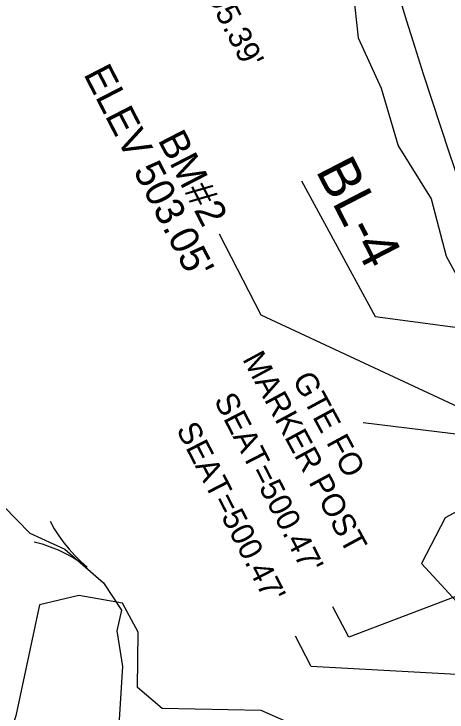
# Model space of a CAD drawing. Extents: x 1534145 to 1537876, y 509021 to 513201.
# Drawn here: x 1535965.3 to 1536040.8, y 511733.6 to 511855.4 of the extents above; entities that cross this region are included whole.
import ezdxf

# ---------------------------------------------------------------- set-up
doc = ezdxf.new("R2010")
doc.units = 0
for name, color, linetype in [('CTL Bench Mark Leader', 7, 'Continuous'), ('CTL Bench Mark Text', 7, 'Continuous'), ('Exist Horizontal Alignment', 7, 'Continuous'), ('Exist Horizontal Baseline Alignment Station Label', 7, 'Continuous'), ('Exist Hydro Stream Flow Arrow CELL', 7, 'Continuous'), ('Exist Hydro Stream or Body of Water', 7, 'Continuous'), ('Exist Right of Way Line', 7, 'Continuous'), ('Exist Structure Major Bridge Seat Top Elevation', 7, 'Continuous'), ('Exist Structure Minor Pipes RCP 15 Inch Invert', 7, 'Continuous'), ('Exist Utilities Other Located Object Leader', 7, 'Continuous'), ('Exist Utilities Other Located Object Text', 7, 'Continuous'), ('Exist Vegetation Woods Line', 7, 'Continuous')]:
    doc.layers.add(name, color=color, linetype=linetype)

msp = doc.modelspace()

# ---------------------------------------------------------------- linework, layer by layer
at = {"layer": 'CTL Bench Mark Leader'}
msp.add_lwpolyline([(1536079.8, 511769.6), (1536008.42, 511802.86), (1536001.11, 511817.02)], dxfattribs=at)
at = {"layer": 'Exist Horizontal Alignment'}
msp.add_arc((1536874.85, 512113.15), 850, 183.46397, 223.9944, dxfattribs=at)
at = {"layer": 'Exist Horizontal Baseline Alignment Station Label'}
msp.add_lwpolyline([(1536015.47, 511826.3), (1536028.3, 511802.67), (1536066.28, 511797.6)], dxfattribs=at)
at = {"layer": 'Exist Hydro Stream Flow Arrow CELL'}
msp.add_line((1535974.11, 511762.02), (1535974.11, 511762.02), dxfattribs=at)
for points in [[(1535971.6, 511766.92), (1535972.28, 511765.62), (1535973.11, 511764.37), (1535973.95, 511763.15), (1535974.86, 511762.03), (1535975.86, 511760.94), (1535976.93, 511759.89), (1535978.03, 511758.92)], [(1535968.77, 511763.32), (1535970.19, 511762.97), (1535971.59, 511762.45), (1535972.97, 511761.91), (1535974.27, 511761.29), (1535975.57, 511760.57), (1535976.84, 511759.77), (1535978.03, 511758.92)]]:
    msp.add_lwpolyline(points, dxfattribs=at)
at = {"layer": 'Exist Hydro Stream or Body of Water'}
msp.add_lwpolyline([(1535946.75, 511770.51), (1535959.25, 511770.95), (1535963.42, 511769.55), (1535968.05, 511764.86), (1535974.11, 511762.02), (1535980.91, 511756.14), (1535984.02, 511751.42), (1535983.21, 511747.78), (1535984.2, 511741.56), (1535983.63, 511732.34), (1535984.87, 511726.77), (1535984.64, 511723.27), (1535982.14, 511717.09)], dxfattribs=at)
at = {"layer": 'Exist Right of Way Line'}
msp.add_arc((1536874.85, 512113.15), 880, 183.46397, 223.9944, dxfattribs=at)
at = {"layer": 'Exist Structure Major Bridge Seat Top Elevation'}
for points in [[(1536083.97, 511769.63), (1536023.69, 511746.66), (1536020.94, 511751.99)], [(1536099.56, 511737.01), (1536017.12, 511741.55), (1536014.37, 511746.89)]]:
    msp.add_lwpolyline(points, dxfattribs=at)
at = {"layer": 'Exist Utilities Other Located Object Leader'}
msp.add_lwpolyline([(1536070, 511778.73), (1536026.2, 511784.1)], dxfattribs=at)
at = {"layer": 'Exist Vegetation Woods Line'}
for points in [[(1535954.04, 511853.16), (1535966.02, 511858.51), (1535970.6, 511870.91), (1535970.15, 511875.74), (1535974.71, 511881.1), (1535988.59, 511888.03), (1536000.97, 511889.59), (1536009.77, 511882.21), (1536016.62, 511871.88), (1536024.49, 511859.38), (1536025.31, 511851.26), (1536029.33, 511842.5), (1536032.33, 511832.43), (1536038.1, 511823.16), (1536040.7, 511813.2), (1536045, 511805.29), (1536048.58, 511798.25), (1536049.61, 511787.84), (1536052.62, 511782.04), (1536051.19, 511773.44), (1536046.44, 511770.73), (1536040.52, 511767.51), (1536036.36, 511759.53)], [(1536036.36, 511759.53), (1536044.62, 511750.63), (1536055.14, 511742.04), (1536060.04, 511732.9), (1536050.95, 511727.97), (1536041.11, 511727.43), (1536031.81, 511731.1), (1536016.97, 511730.12), (1536008.4, 511733.89), (1535991.12, 511734.21)], [(1535991.12, 511734.21), (1535986.81, 511737.92), (1535986.94, 511747.54), (1535984.2, 511752.64), (1535976.56, 511753.95), (1535969.71, 511752.34), (1535965.6, 511732.98), (1535962.22, 511722.69), (1535952.18, 511720.66), (1535941.4, 511721.15), (1535936.11, 511722.2), (1535929.54, 511726.22), (1535927.65, 511729.7), (1535915.01, 511733.19), (1535905.33, 511731.62), (1535892.86, 511729.74), (1535881.99, 511734.13), (1535876.96, 511731.39), (1535869.12, 511724.27)]]:
    msp.add_lwpolyline(points, dxfattribs=at)

# ---------------------------------------------------------------- texts
at = {"layer": 'CTL Bench Mark Text'}
for s, p in [("ELEV 503.05'", (1535977.31, 511844.96)), ('BM#2', (1535990.28, 511833.48))]:
    msp.add_text(s, height=5, rotation=297.2825, dxfattribs=at).set_placement(p)
at = {"layer": 'Exist Horizontal Baseline Alignment Station Label'}
msp.add_text('BL-4', height=7, rotation=297.2824, dxfattribs=at).set_placement((1536017.85, 511828.11))
at = {"layer": 'Exist Structure Major Bridge Seat Top Elevation'}
for p in [(1536000.09, 511788.06), (1535993.51, 511782.96)]:
    msp.add_text("SEAT=500.47'", height=4, rotation=297.2825, dxfattribs=at).set_placement(p)
at = {"layer": 'Exist Structure Minor Pipes RCP 15 Inch Invert'}
msp.add_text("INV=495.39'", height=4, rotation=297.2825, dxfattribs=at).set_placement((1535992.02, 511871.77))
at = {"layer": 'Exist Utilities Other Located Object Text'}
for s, p in [('MARKER POST', (1536005.04, 511795.21)), ('GTE FO ', (1536013.76, 511791.69))]:
    msp.add_text(s, height=4, rotation=298.3612, dxfattribs=at).set_placement(p)

doc.saveas('drawing.dxf')
